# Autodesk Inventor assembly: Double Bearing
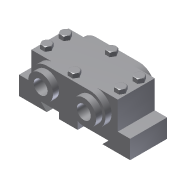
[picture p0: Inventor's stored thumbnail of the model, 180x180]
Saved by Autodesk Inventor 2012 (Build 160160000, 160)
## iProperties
Shininess: 64.0
Length Units: 11269
Angle Units: 11279
Time Units: 11290
Mass Units: 11283
Length Display Precision: 3
Angle Display Precision: 2
Created: 2002-02
Part Number: Double Bearing
Document SubType Name: Assembly
Designer: ***
Density: 0.0
Volumn: 0.0
Area: 0.0
PropertySet Name: Model Information
Control State: 0
Master: False
Checked Out: False
Author: ***
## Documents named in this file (5)
- C:\Users\CadCim\Documents\SAILESH\inventor-2011-fact-prt\c1211inv_2012-prt\c12_inv_2012_prt\Tutorials\c12_tut02_inv\Double Bearing.iam
- C:\Users\CadCim\Documents\SAILESH\inventor-2011-fact-prt\c1211inv_2012-prt\Tutorials\c12-tut02-inv\Base.ipt
- C:\Users\CadCim\Documents\SAILESH\inventor-2011-fact-prt\c1211inv_2012-prt\Tutorials\c12-tut02-inv\Cap.ipt
- C:\Users\CadCim\Documents\SAILESH\inventor-2011-fact-prt\c1211inv_2012-prt\Tutorials\c12-tut02-inv\Bushing.ipt
- C:\Users\CadCim\Documents\SAILESH\inventor-2011-fact-prt\c1211inv_2012-prt\Tutorials\c12-tut02-inv\Bolt.ipt
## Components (10 placed, 4 different names)
1. Base:1 — Insert:1, Insert:2
2. Cap:1 — Insert:1, Insert:2, Insert:3, Insert:4, Insert:5, Insert:6
3. Bushing:1 — Insert:3
4. Bushing:2 — Insert:4
5. Bolt:1 — Insert:5
6. Bolt:6
7. Bolt:7
8. Bolt:8
9. Bolt:5 — Insert:6
10. Bolt:9
## Component patterns: Component Pattern 1 (4 elements), Component Pattern 2 (2 elements)
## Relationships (6: Insert 6)
- Insert:1: Base:1 ↔ Cap:1
- Insert:2: Base:1 ↔ Cap:1
- Insert:3: Cap:1 ↔ Bushing:1
- Insert:4: Cap:1 ↔ Bushing:2
- Insert:5: Cap:1 ↔ Bolt:1
- Insert:6: Cap:1 ↔ Bolt:5
